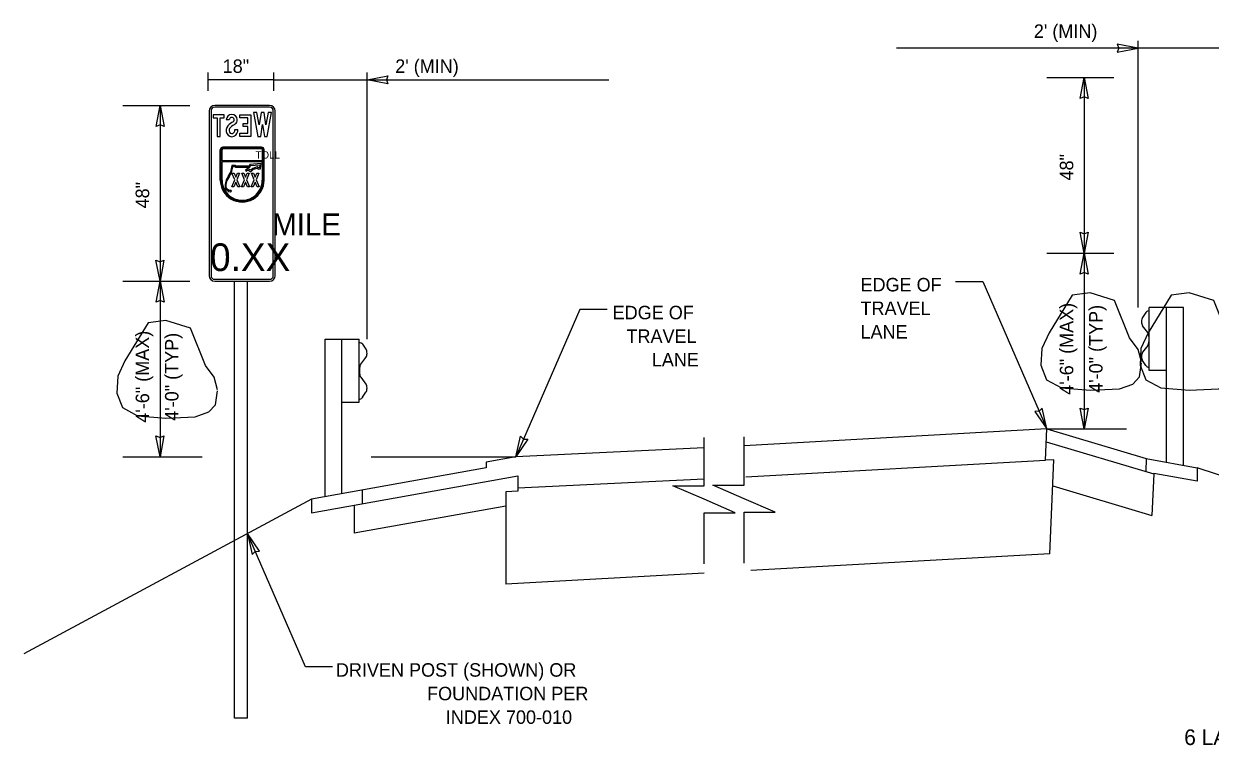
# Model space of a CAD drawing. Extents: x 57428 to 58066, y 11696 to 12105.
# Drawn here: x 57464.3 to 57710.6, y 11954.7 to 12104.5 of the extents above; entities that cross this region are included whole.
import ezdxf

# ---------------------------------------------------------------- set-up
doc = ezdxf.new("R2010")
doc.units = 0
for name, color, linetype in [('52', 7, 'Continuous'), ('62', 7, 'Continuous'), ('Default', 7, 'Continuous'), ('DimLines_dp', 7, 'Continuous'), ('NonPlottingEle_dp', 7, 'Continuous'), ('SignPanel', 7, 'Continuous'), ('TextTables', 7, 'Continuous'), ('XSGrdLine_ex', 7, 'Continuous')]:
    doc.layers.add(name, color=color, linetype=linetype)

msp = doc.modelspace()

# ---------------------------------------------------------------- linework, layer by layer
at = {"layer": '52'}
for p, q in [((57676.68, 12020.37), (57693.18, 12020.37)), ((57484.81, 12014.58), (57501.31, 12014.58)), ((57536.38, 12014.58), (57566.41, 12014.58))]:
    msp.add_line(p, q, dxfattribs=at)
at = {"layer": '62'}
for points in [[(57696.33, 12034.31), (57695.63, 12036.91), (57693.83, 12039.32), (57690.73, 12047.07), (57685.63, 12048.67), (57681.93, 12048.17), (57677.12, 12040.32), (57675.62, 12037.11), (57675.42, 12033.61), (57676.62, 12030.61), (57679.73, 12028.9), (57685.63, 12028.4), (57691.73, 12028.7), (57694.53, 12029.7), (57695.93, 12031.21), (57696.33, 12034.11)], [(57716.92, 12034.31), (57716.22, 12036.91), (57714.42, 12039.32), (57711.32, 12047.07), (57706.22, 12048.67), (57702.51, 12048.17), (57697.71, 12040.32), (57696.21, 12037.11), (57696.01, 12033.61), (57697.21, 12030.61), (57700.31, 12028.9), (57706.22, 12028.4), (57712.32, 12028.7), (57715.12, 12029.7), (57716.52, 12031.21), (57716.92, 12034.11)], [(57504.47, 12028.52), (57503.77, 12031.12), (57501.97, 12033.52), (57498.86, 12041.28), (57493.76, 12042.88), (57490.06, 12042.38), (57485.26, 12034.52), (57483.76, 12031.32), (57483.56, 12027.82), (57484.76, 12024.81), (57487.86, 12023.11), (57493.76, 12022.61), (57499.86, 12022.91), (57502.67, 12023.91), (57504.07, 12025.41), (57504.47, 12028.32)]]:
    msp.add_lwpolyline(points, dxfattribs=at)
at = {"layer": 'Default'}
for points in [[(57605.5, 11992.39), (57605.5, 12002.95), (57611.96, 12002.95), (57605.5, 12005.76), (57599.04, 12008.57), (57605.5, 12008.57), (57605.5, 12018.57)], [(57613.8, 11992.52), (57613.8, 12003.08), (57620.26, 12003.08), (57613.8, 12005.89), (57607.34, 12008.71), (57613.8, 12008.71), (57613.8, 12018.71)]]:
    msp.add_lwpolyline(points, dxfattribs=at)
at = {"layer": 'DimLines_dp'}
for p, q in [((57695.64, 12045.58), (57695.64, 12100.98)), ((57714.97, 12099.43), (57645.43, 12099.43)), ((57695.64, 12099.43), (57691.29, 12100.27)), ((57691.29, 12100.27), (57691.62, 12099.43)), ((57691.62, 12099.43), (57691.29, 12098.62)), ((57691.29, 12098.62), (57695.64, 12099.43)), ((57502.51, 12090.57), (57502.51, 12094.4)), ((57516.2, 12090.57), (57516.2, 12094.4)), ((57535.53, 12039), (57535.53, 12094.4)), ((57535.53, 12092.86), (57539.88, 12093.7)), ((57539.88, 12093.7), (57539.55, 12092.86)), ((57676.68, 12093.37), (57690.6, 12093.37)), ((57683.61, 12089.02), (57684.42, 12093.37)), ((57684.42, 12093.37), (57684.42, 12056.87)), ((57684.42, 12093.37), (57685.26, 12089.02)), ((57516.2, 12092.86), (57502.51, 12092.86)), ((57516.2, 12092.86), (57585.74, 12092.86)), ((57539.88, 12092.05), (57535.53, 12092.86)), ((57539.55, 12092.86), (57539.88, 12092.05)), ((57684.42, 12089.35), (57683.61, 12089.02)), ((57685.26, 12089.02), (57684.42, 12089.35)), ((57484.81, 12087.57), (57498.74, 12087.57)), ((57491.74, 12083.22), (57492.55, 12087.57)), ((57492.55, 12087.57), (57492.55, 12051.07)), ((57492.55, 12087.57), (57493.39, 12083.22)), ((57492.55, 12083.55), (57491.74, 12083.22)), ((57493.39, 12083.22), (57492.55, 12083.55)), ((57684.42, 12056.87), (57683.58, 12061.22)), ((57683.58, 12061.22), (57684.42, 12060.89)), ((57684.42, 12056.87), (57683.58, 12061.22)), ((57683.58, 12061.22), (57684.42, 12060.89)), ((57684.42, 12060.89), (57685.23, 12061.22)), ((57685.23, 12061.22), (57684.42, 12056.87)), ((57684.42, 12060.89), (57685.23, 12061.22)), ((57685.23, 12061.22), (57684.42, 12056.87)), ((57676.68, 12056.87), (57690.6, 12056.87)), ((57683.61, 12052.52), (57684.42, 12056.87)), ((57684.42, 12056.87), (57684.42, 12020.37)), ((57684.42, 12056.87), (57685.26, 12052.52)), ((57492.55, 12051.07), (57491.71, 12055.42)), ((57491.71, 12055.42), (57492.55, 12055.09)), ((57492.55, 12051.07), (57491.71, 12055.42)), ((57491.71, 12055.42), (57492.55, 12055.09)), ((57492.55, 12055.09), (57493.36, 12055.42)), ((57493.36, 12055.42), (57492.55, 12051.07)), ((57492.55, 12055.09), (57493.36, 12055.42)), ((57493.36, 12055.42), (57492.55, 12051.07)), ((57684.42, 12052.85), (57683.61, 12052.52)), ((57685.26, 12052.52), (57684.42, 12052.85)), ((57484.81, 12051.07), (57498.74, 12051.07)), ((57491.74, 12046.72), (57492.55, 12051.07)), ((57492.55, 12051.07), (57492.55, 12014.58)), ((57492.55, 12051.07), (57493.39, 12046.72)), ((57657.71, 12050.98), (57663.36, 12050.98)), ((57663.36, 12050.98), (57676.68, 12020.37)), ((57492.55, 12047.05), (57491.74, 12046.72)), ((57493.39, 12046.72), (57492.55, 12047.05)), ((57579.73, 12045.19), (57566.41, 12014.57)), ((57585.38, 12045.19), (57579.73, 12045.19)), ((57675.71, 12024.69), (57675.08, 12024.05)), ((57676.68, 12020.37), (57675.71, 12024.69)), ((57684.42, 12020.37), (57683.58, 12024.72)), ((57683.58, 12024.72), (57684.42, 12024.39)), ((57684.42, 12024.39), (57685.23, 12024.72)), ((57685.23, 12024.72), (57684.42, 12020.37)), ((57675.08, 12024.05), (57674.2, 12024.03)), ((57674.2, 12024.03), (57676.68, 12020.37)), ((57492.55, 12014.58), (57491.71, 12018.93)), ((57491.71, 12018.93), (57492.55, 12018.6)), ((57492.55, 12018.6), (57493.36, 12018.93)), ((57493.36, 12018.93), (57492.55, 12014.58)), ((57566.41, 12014.57), (57567.37, 12018.9)), ((57568.89, 12018.24), (57566.41, 12014.57)), ((57567.37, 12018.9), (57568.01, 12018.26)), ((57568.01, 12018.26), (57568.89, 12018.24)), ((57522.73, 11970.95), (57510.69, 11998.63)), ((57510.69, 11998.63), (57511.65, 11994.3)), ((57513.17, 11994.96), (57510.69, 11998.63)), ((57511.65, 11994.3), (57512.29, 11994.94)), ((57512.29, 11994.94), (57513.17, 11994.96)), ((57528.38, 11970.95), (57522.73, 11970.95))]:
    msp.add_line(p, q, dxfattribs=at)
at = {"layer": 'NonPlottingEle_dp'}
for p, q in [((57508.03, 11997.2), (57508.03, 12051.07)), ((57510.69, 11998.63), (57510.69, 12051.07)), ((57508.03, 11960.3), (57508.03, 11997.2)), ((57510.69, 11960.3), (57510.69, 11998.63)), ((57510.69, 11960.3), (57508.03, 11960.3))]:
    msp.add_line(p, q, dxfattribs=at)
at = {"layer": 'SignPanel'}
for p, q in [((57506.91, 12084.56), (57506.3, 12084.56)), ((57506.91, 12084.56), (57506.3, 12084.56)), ((57506.91, 12084.56), (57506.3, 12084.56)), ((57508.11, 12082.56), (57508.73, 12082.56)), ((57508.11, 12082.56), (57508.73, 12082.56)), ((57508.11, 12082.56), (57508.73, 12082.56)), ((57513.6, 12078.91), (57505.61, 12078.91)), ((57513.6, 12078.71), (57505.61, 12078.71)), ((57513.6, 12078.52), (57505.61, 12078.52)), ((57505.04, 12072.06), (57505.04, 12078.34)), ((57505.24, 12072.06), (57505.24, 12078.34)), ((57505.43, 12076.05), (57505.43, 12078.34)), ((57513.79, 12076.05), (57505.43, 12076.05)), ((57513.79, 12076.05), (57513.79, 12078.34)), ((57513.98, 12072.06), (57513.98, 12078.34)), ((57514.17, 12072.06), (57514.17, 12078.34)), ((57505.43, 12072.06), (57505.43, 12075.86)), ((57513.79, 12075.86), (57505.43, 12075.86)), ((57507.16, 12073.69), (57506.71, 12072.96)), ((57506.94, 12072.9), (57507.38, 12073.6)), ((57507.49, 12075.12), (57507.16, 12073.69)), ((57507.38, 12073.6), (57507.68, 12074.89)), ((57508.23, 12075.12), (57507.49, 12075.12)), ((57507.68, 12074.89), (57508.11, 12074.89)), ((57508.11, 12074.89), (57508.21, 12074.74)), ((57508.21, 12074.74), (57511.22, 12074.74)), ((57508.33, 12074.97), (57508.23, 12075.12)), ((57511.06, 12074.97), (57508.33, 12074.97)), ((57510.77, 12074.45), (57510.27, 12074.11)), ((57510.27, 12074.11), (57510.4, 12073.92)), ((57510.4, 12073.92), (57510.77, 12074.17)), ((57511.38, 12074.09), (57510.77, 12074.45)), ((57510.77, 12074.17), (57511.41, 12073.8)), ((57511.19, 12075.31), (57511.06, 12074.97)), ((57513.57, 12075.5), (57511.19, 12075.31)), ((57511.22, 12074.74), (57511.36, 12075.09)), ((57511.36, 12075.09), (57513.3, 12075.24)), ((57511.83, 12074.5), (57511.38, 12074.09)), ((57511.41, 12073.8), (57511.95, 12074.3)), ((57512.75, 12074.8), (57511.83, 12074.5)), ((57511.95, 12074.3), (57512.7, 12074.55)), ((57512.32, 12075.16), (57512.32, 12075.16)), ((57512.7, 12074.55), (57512.95, 12074.35)), ((57513.02, 12074.59), (57512.75, 12074.8)), ((57512.95, 12074.35), (57513.41, 12074.41)), ((57513.2, 12074.61), (57513.02, 12074.59)), ((57513.3, 12075.24), (57513.2, 12074.61)), ((57513.41, 12074.41), (57513.57, 12075.5)), ((57513.79, 12072.06), (57513.79, 12075.86)), ((57506.3, 12072.11), (57506.05, 12071.18)), ((57506.05, 12071.18), (57506.05, 12070.32)), ((57506.28, 12071.15), (57506.51, 12072.01)), ((57506.28, 12070.43), (57506.28, 12071.15)), ((57506.71, 12072.78), (57506.3, 12072.11)), ((57506.51, 12072.01), (57506.94, 12072.72)), ((57506.71, 12072.96), (57506.71, 12072.78)), ((57506.94, 12072.72), (57506.94, 12072.9)), ((57506.05, 12070.32), (57506.8, 12069.7)), ((57506.9, 12069.92), (57506.28, 12070.43)), ((57506.8, 12069.7), (57507.16, 12069.62)), ((57507.11, 12069.87), (57506.9, 12069.92)), ((57507.25, 12069.96), (57507.11, 12069.87)), ((57507.16, 12069.62), (57507.38, 12069.78)), ((57507.38, 12069.78), (57507.25, 12069.96))]:
    msp.add_line(p, q, dxfattribs=at)
for points in [[(57502.76, 12086.43), (57502.76, 12052.21)], [(57503.14, 12086.43), (57503.14, 12052.21)], [(57515.31, 12087.57), (57503.9, 12087.57)], [(57515.31, 12087.19), (57503.9, 12087.19)], [(57516.07, 12052.21), (57516.07, 12086.43)], [(57516.45, 12052.21), (57516.45, 12086.43)], [(57503.9, 12051.45), (57515.31, 12051.45)], [(57503.9, 12051.07), (57515.31, 12051.07)]]:
    msp.add_lwpolyline(points, dxfattribs=at)
for points in [[(57514.54, 12083.53), (57514.14, 12086.1), (57513.53, 12086.1), (57513.13, 12083.53), (57512.68, 12086.1), (57511.98, 12086.1), (57512.86, 12081.14), (57513.45, 12081.14), (57513.84, 12083.62), (57514.23, 12081.14), (57514.81, 12081.14), (57515.69, 12086.1), (57515, 12086.1)], [(57514.54, 12083.53), (57514.14, 12086.1), (57513.53, 12086.1), (57513.13, 12083.53), (57512.68, 12086.1), (57511.98, 12086.1), (57512.86, 12081.14), (57513.45, 12081.14), (57513.84, 12083.62), (57514.23, 12081.14), (57514.81, 12081.14), (57515.69, 12086.1), (57515, 12086.1)], [(57514.54, 12083.53), (57514.14, 12086.1), (57513.53, 12086.1), (57513.13, 12083.53), (57512.68, 12086.1), (57511.98, 12086.1), (57512.86, 12081.14), (57513.45, 12081.14), (57513.84, 12083.62), (57514.23, 12081.14), (57514.81, 12081.14), (57515.69, 12086.1), (57515, 12086.1)], [(57505.05, 12085.02), (57505.87, 12085.02), (57505.87, 12085.65), (57503.61, 12085.65), (57503.61, 12085.02), (57504.43, 12085.02), (57504.43, 12081.14), (57505.05, 12081.14)], [(57505.05, 12085.02), (57505.87, 12085.02), (57505.87, 12085.65), (57503.61, 12085.65), (57503.61, 12085.02), (57504.43, 12085.02), (57504.43, 12081.14), (57505.05, 12081.14)], [(57505.05, 12085.02), (57505.87, 12085.02), (57505.87, 12085.65), (57503.61, 12085.65), (57503.61, 12085.02), (57504.43, 12085.02), (57504.43, 12081.14), (57505.05, 12081.14)], [(57510.76, 12081.78), (57510.76, 12083.22), (57509.79, 12083.22), (57509.79, 12083.85), (57510.76, 12083.85), (57510.76, 12085.02), (57509.12, 12085.02), (57509.12, 12085.65), (57511.38, 12085.65), (57511.38, 12081.14), (57509.12, 12081.14), (57509.12, 12081.78)], [(57510.76, 12081.78), (57510.76, 12083.22), (57509.79, 12083.22), (57509.79, 12083.85), (57510.76, 12083.85), (57510.76, 12085.02), (57509.12, 12085.02), (57509.12, 12085.65), (57511.38, 12085.65), (57511.38, 12081.14), (57509.12, 12081.14), (57509.12, 12081.78)], [(57510.76, 12081.78), (57510.76, 12083.22), (57509.79, 12083.22), (57509.79, 12083.85), (57510.76, 12083.85), (57510.76, 12085.02), (57509.12, 12085.02), (57509.12, 12085.65), (57511.38, 12085.65), (57511.38, 12081.14), (57509.12, 12081.14), (57509.12, 12081.78)], [(57508.69, 12070.64), (57508.28, 12071.62), (57507.87, 12070.64), (57507.44, 12070.64), (57508.06, 12072.13), (57507.49, 12073.49), (57507.92, 12073.49), (57508.28, 12072.64), (57508.64, 12073.49), (57509.06, 12073.49), (57508.49, 12072.13), (57509.11, 12070.64)], [(57510.7, 12070.64), (57510.29, 12071.62), (57509.88, 12070.64), (57509.46, 12070.64), (57510.08, 12072.13), (57509.51, 12073.49), (57509.93, 12073.49), (57510.29, 12072.64), (57510.65, 12073.49), (57511.08, 12073.49), (57510.51, 12072.13), (57511.13, 12070.64)], [(57512.72, 12070.64), (57512.31, 12071.62), (57511.9, 12070.64), (57511.47, 12070.64), (57512.1, 12072.13), (57511.52, 12073.49), (57511.95, 12073.49), (57512.31, 12072.64), (57512.67, 12073.49), (57513.09, 12073.49), (57512.52, 12072.13), (57513.14, 12070.64)]]:
    msp.add_lwpolyline(points, close=True, dxfattribs=at)
for centre, radius, start, end in [((57503.9, 12086.43), 1.14, 90, 180), ((57503.9, 12086.43), 0.76, 90, 180), ((57515.31, 12086.43), 1.14, 0, 90), ((57515.31, 12086.43), 0.76, 0, 90), ((57503.9, 12052.21), 1.14, 180, 270), ((57503.9, 12052.21), 0.76, 180, 270), ((57515.31, 12052.21), 1.14, 270, 0), ((57515.31, 12052.21), 0.76, 270, 0)]:
    msp.add_arc(centre, radius, start, end, dxfattribs=at)
for centre, major_axis, ratio, start_param, end_param in [((57507.45, 12084.54), (0, -1.17), 0.981197, 1.634182, 4.688511), ((57507.45, 12084.54), (0, -1.17), 0.981197, 1.634182, 4.688511), ((57507.45, 12084.54), (0, -1.17), 0.981197, 1.634182, 4.688511), ((57509.76, 12080.4), (0, -4.32), 0.981197, 3.642536, 3.961892), ((57509.76, 12080.4), (0, -4.32), 0.981197, 3.642536, 3.961892), ((57509.76, 12080.4), (0, -4.32), 0.981197, 3.642536, 3.961892), ((57507.45, 12084.52), (0, -0.55), 0.981197, 2.28404, 4.637874), ((57507.45, 12084.52), (0, -0.55), 0.981197, 2.28404, 4.637874), ((57507.45, 12084.52), (0, -0.55), 0.981197, 2.28404, 4.637874), ((57510.3, 12079.71), (0, -4.56), 0.981197, 3.63779, 3.909641), ((57510.3, 12079.71), (0, -4.56), 0.981197, 3.63779, 3.909641), ((57510.3, 12079.71), (0, -4.56), 0.981197, 3.63779, 3.909641), ((57507.52, 12084.59), (0, -0.453), 0.981197, 0.484634, 2.267813), ((57507.52, 12084.59), (0, -0.453), 0.981197, 0.484634, 2.267813), ((57507.52, 12084.59), (0, -0.453), 0.981197, 0.484634, 2.267813), ((57507.56, 12084.57), (0, -1.05), 0.981197, 0.629826, 1.606762), ((57507.56, 12084.57), (0, -1.05), 0.981197, 0.629826, 1.606762), ((57507.56, 12084.57), (0, -1.05), 0.981197, 0.629826, 1.606762), ((57507.64, 12082.37), (0, -1.4), 0.981197, 3.939023, 5.163791), ((57507.64, 12082.37), (0, -1.4), 0.981197, 3.939023, 5.163791), ((57507.64, 12082.37), (0, -1.4), 0.981197, 3.939023, 5.163791), ((57507.49, 12082.31), (0, -1.23), 0.981197, 5.173086, 6.638731), ((57507.49, 12082.31), (0, -1.23), 0.981197, 5.173086, 6.638731), ((57507.49, 12082.31), (0, -1.23), 0.981197, 5.173086, 6.638731), ((57507.65, 12082.37), (0, -0.78), 0.981197, 3.79238, 5.170369), ((57507.65, 12082.37), (0, -0.78), 0.981197, 3.79238, 5.170369), ((57507.65, 12082.37), (0, -0.78), 0.981197, 3.79238, 5.170369), ((57507.46, 12082.29), (0, -0.572), 0.981197, 5.194718, 7.162991), ((57507.46, 12082.29), (0, -0.572), 0.981197, 5.194718, 7.162991), ((57507.46, 12082.29), (0, -0.572), 0.981197, 5.194718, 7.162991), ((57507.23, 12082.52), (0, -0.897), 0.981197, 0.859453, 1.616836), ((57507.29, 12082.49), (0, -1.47), 0.981197, 0.439911, 1.615229), ((57507.23, 12082.52), (0, -0.897), 0.981197, 0.859453, 1.616836), ((57507.29, 12082.49), (0, -1.47), 0.981197, 0.439911, 1.615229), ((57507.23, 12082.52), (0, -0.897), 0.981197, 0.859453, 1.616836), ((57507.29, 12082.49), (0, -1.47), 0.981197, 0.439911, 1.615229), ((57505.62, 12078.33), (0, 0.57), 0.9997, 0, 1.570796), ((57505.62, 12078.33), (0, 0.38), 0.9997, 0, 1.570796), ((57505.62, 12078.33), (0, 0.19), 0.9997, 0, 1.570796), ((57513.6, 12078.33), (0, 0.57), 0.9997, 4.712389, 6.283185), ((57513.6, 12078.33), (0, 0.38), 0.9997, 4.712389, 6.283185), ((57513.6, 12078.33), (0, 0.19), 0.9997, 4.712389, 6.283185), ((57509.61, 12072.06), (0, 4.56), 0.9997, 1.570796, 4.712389), ((57509.61, 12072.06), (0, 4.37), 0.9997, 1.570796, 4.712389), ((57509.61, 12072.06), (0, 4.18), 0.9997, 1.570796, 4.712389)]:
    msp.add_ellipse(centre, major_axis=major_axis, ratio=ratio, start_param=start_param, end_param=end_param, dxfattribs=at)
at = {"layer": 'XSGrdLine_ex'}
for p, q in [((57697.23, 12044.57), (57696.53, 12043.53)), ((57697.92, 12045.01), (57697.45, 12044.78)), ((57705.04, 12045.58), (57697.93, 12045.58)), ((57697.93, 12032.49), (57697.93, 12045.58)), ((57701.54, 12013.47), (57701.54, 12045.58)), ((57705.04, 12012.84), (57705.04, 12045.58)), ((57697.63, 12040.42), (57696.56, 12041.82)), ((57697.86, 12039.6), (57697.86, 12038.5)), ((57526.81, 12006.27), (57526.81, 12039)), ((57526.81, 12039), (57533.91, 12039)), ((57530.3, 12006.9), (57530.3, 12039)), ((57533.91, 12025.91), (57533.91, 12039)), ((57533.92, 12038.43), (57534.39, 12038.2)), ((57534.62, 12037.99), (57535.31, 12036.95)), ((57697.63, 12037.7), (57696.56, 12036.29)), ((57534.21, 12033.84), (57535.28, 12035.24)), ((57697.23, 12033.54), (57696.53, 12034.57)), ((57533.99, 12033.02), (57533.99, 12031.92)), ((57697.92, 12033.1), (57697.45, 12033.31)), ((57701.54, 12032.49), (57697.93, 12032.49)), ((57534.21, 12031.12), (57535.28, 12029.71)), ((57533.92, 12026.52), (57534.39, 12026.73)), ((57534.62, 12026.96), (57535.31, 12027.99)), ((57530.3, 12025.91), (57533.91, 12025.91)), ((57676.68, 12020.37), (57613.8, 12016.89)), ((57676.39, 12013.86), (57676.68, 12020.37)), ((57676.68, 12020.37), (57697.32, 12014.23)), ((57676.56, 12017.7), (57698.85, 12011.07)), ((57566.41, 12014.57), (57560.25, 12013.46)), ((57560.25, 12012.29), (57523.97, 12005.76)), ((57560.25, 12013.46), (57560.25, 12012.29)), ((57614.16, 12010.41), (57676.39, 12013.86)), ((57678.14, 12013.95), (57676.39, 12013.86)), ((57677.27, 11994.41), (57678.14, 12013.95)), ((57697.32, 12014.23), (57697.2, 12011.56)), ((57697.32, 12014.23), (57707.87, 12012.33)), ((57751.86, 11997.83), (57707.87, 12012.33)), ((57707.87, 12012.33), (57707.87, 12009.5)), ((57523.97, 12002.92), (57566.82, 12010.63)), ((57566.82, 12010.63), (57566.82, 12007.48)), ((57698.85, 12011.07), (57698.47, 12002.43)), ((57707.87, 12009.5), (57698.85, 12011.12)), ((57534.53, 12007.66), (57534.53, 12004.82)), ((57566.82, 12007.48), (57564.35, 12007.33)), ((57564.35, 12007.33), (57564.35, 11988.15)), ((57677.9, 12008.55), (57698.47, 12002.43)), ((57523.97, 12005.76), (57464.25, 11973.7)), ((57523.97, 12005.76), (57523.97, 12002.92)), ((57532.83, 12004.51), (57532.83, 11998.7)), ((57564.35, 12004.37), (57532.83, 11998.7)), ((57677.27, 11994.41), (57615.23, 11990.97)), ((57605.5, 11990.43), (57564.35, 11988.15))]:
    msp.add_line(p, q, dxfattribs=at)
for points in [[(57605.5, 12016.43), (57566.41, 12014.57)], [(57605.5, 12009.93), (57566.82, 12008.09)]]:
    msp.add_lwpolyline(points, dxfattribs=at)
for centre, major_axis, start_param, end_param in [((57697.61, 12043.53), (0, 1.28), 0.24129, 0.636649), ((57696.84, 12042.69), (0, -1.05), 3.777871, 5.70598), ((57697.37, 12039.59), (0, 0.976), 4.723749, 5.70602), ((57534.24, 12036.95), (0, 1.28), 5.646537, 6.041895), ((57535, 12036.11), (0, -1.05), 0.577206, 2.505315), ((57697.37, 12038.51), (0, 0.976), 3.718758, 4.701029), ((57696.84, 12035.41), (0, 1.05), 0.577206, 2.505315), ((57534.48, 12033.01), (0, -0.976), 3.718758, 4.701029), ((57534.48, 12031.93), (0, -0.976), 4.723749, 5.70602), ((57697.61, 12034.56), (0, -1.28), 5.646537, 6.041895), ((57535, 12028.83), (0, 1.05), 3.777871, 5.70598), ((57534.24, 12027.99), (0, -1.28), 0.24129, 0.636649)]:
    msp.add_ellipse(centre, major_axis=major_axis, ratio=0.5, start_param=start_param, end_param=end_param, dxfattribs=at)

# ---------------------------------------------------------------- texts
at = {"layer": 'DimLines_dp'}
for s, p in [("2' (MIN)", (57673.97, 12101.59)), ('18"', (57505.55, 12094.33)), ("2' (MIN)", (57541.38, 12094.33)), ('EDGE OF ', (57637.98, 12048.94)), ('TRAVEL ', (57637.98, 12044.04)), ('EDGE OF ', (57586.52, 12043.15)), ('LANE', (57637.98, 12039.14)), ('TRAVEL ', (57589.39, 12038.25)), ('LANE', (57594.65, 12033.35)), ('DRIVEN POST (SHOWN) OR', (57529.06, 11968.92)), ('FOUNDATION PER', (57547.99, 11964.02)), ('INDEX 700-010', (57551.88, 11959.12))]:
    msp.add_text(s, height=2.8, dxfattribs=at).set_placement(p)
for s, p in [('48"', (57682.16, 12071.98)), ('48"', (57490.29, 12066.18)), ('4\'-6" (MAX)', (57682.16, 12027.47)), ('4\'-0" (TYP)', (57688.24, 12027.87)), ('4\'-6" (MAX)', (57490.29, 12021.67)), ('4\'-0" (TYP)', (57496.38, 12022.07))]:
    msp.add_text(s, height=2.8, rotation=90, dxfattribs=at).set_placement(p)
at = {"layer": 'SignPanel'}
for s, height, p in [('TOLL', 1.519, (57512.36, 12076.53)), ('MILE', 4.562, (57515.86, 12060.57)), ('0.XX', 5.75, (57502.93, 12053.17))]:
    msp.add_text(s, height=height, rotation=360, dxfattribs=at).set_placement(p)
at = {"layer": 'TextTables'}
msp.add_text("6 LANES OR MORE - MEDIANS 40' OR LESS", height=3.2524, dxfattribs=at).set_placement((57705.19, 11954.72))

doc.saveas('drawing.dxf')
